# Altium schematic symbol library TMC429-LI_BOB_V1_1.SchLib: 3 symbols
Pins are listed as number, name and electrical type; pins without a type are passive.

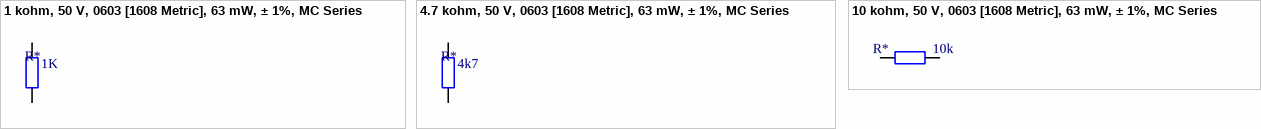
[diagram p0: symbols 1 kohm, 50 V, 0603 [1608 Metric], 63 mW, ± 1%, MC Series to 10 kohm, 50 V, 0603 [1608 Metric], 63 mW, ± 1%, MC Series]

## 1 kohm, 50 V, 0603 [1608 Metric], 63 mW, ± 1%, MC Series
designator R*, comment 1K
1 kohm, 50 V, 0603 [1608 Metric], 63 mW, ± 1%, MC Series; MPN: MC0063W060311K; VoltageRating: 50V; Temp coefficient: *ppm; PowerRating: 63mW; MF: MULTICOMP
footprint R0402 (0402 resistor)
footprint R0603 (0603 resistor)
footprint R0805 (0805 resistor)
footprint R1206 (1206 resistor)
footprint R2512 (2512 resistor)
footprint R0201 (0201 resistor)
footprint R1210 (1210 resistor)
footprint R1812 (1812 resistor)
footprint R2010 (2010 resistor)
footprint R2512 (2512 resistor)
pins: 1, 2

## 4.7 kohm, 50 V, 0603 [1608 Metric], 63 mW, ± 1%, MC Series
designator R*, comment 4k7
4.7 kohm, 50 V, 0603 [1608 Metric], 63 mW, ± 1%, MC Series; MPN: MC0063W060314K7; VoltageRating: 50V; Temp coefficient: *ppm; PowerRating: 63mW; MF: MULTICOMP
footprint R0402 (0402 resistor)
footprint R0603 (0603 resistor)
footprint R0805 (0805 resistor)
footprint R1206 (1206 resistor)
footprint R2512 (2512 resistor)
footprint R0201 (0201 resistor)
footprint R1210 (1210 resistor)
footprint R1812 (1812 resistor)
footprint R2010 (2010 resistor)
footprint R2512 (2512 resistor)
pins: 1, 2

## 10 kohm, 50 V, 0603 [1608 Metric], 63 mW, ± 1%, MC Series
designator R*, comment 10k
10 kohm, 50 V, 0603 [1608 Metric], 63 mW, ± 1%, MC Series; MPN: MC0063W0603110K; VoltageRating: 50V; Temp coefficient: *ppm; PowerRating: 63mW; MF: MULTICOMP
footprint R0402 (0402 resistor)
footprint R0603 (0603 resistor)
footprint R0805 (0805 resistor)
footprint R1206 (1206 resistor)
footprint R2512 (2512 resistor)
footprint R0201 (0201 resistor)
footprint R1210 (1210 resistor)
footprint R1812 (1812 resistor)
footprint R2010 (2010 resistor)
footprint R2512 (2512 resistor)
pins: 1, 2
